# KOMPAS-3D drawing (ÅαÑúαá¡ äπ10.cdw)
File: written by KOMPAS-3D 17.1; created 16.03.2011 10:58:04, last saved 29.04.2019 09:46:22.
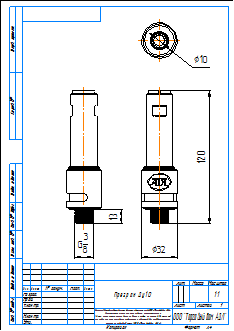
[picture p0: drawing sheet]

Title block, sheet 1: name: Прегран Ду10; material: Внимание! Данный продукт является объектом авторского права ООО «Торговый Дом АДЛ». / Запрещается изменение, копирование, распространение / (в том числе путем копирования на другие сайты и ресурсы в Интернете) / или любое иное использование информации и объектов без предварительного / согласия правообладателя (ООО «Торговый Дом АДЛ»).; scale: 1:1; sheets: 1; organisation: ООО "Торговый дом АДЛ"; sheet format: A4; stored path: C:\Users\tra\Desktop\2д чертежи\Предохранительные клапаны ПРЕГРАН\ПРЕГРАН 495\ПРЕГРАН КПП 495-05-25-ОМЗ\KOMPAS 2D\Прегран Ду10.cdw

Views: Спереди 1, Проекционный вид 5, Проекционный вид 6
Dimensions and other numbers on the sheet: 120; 32; 13; 10; 1:1; 1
